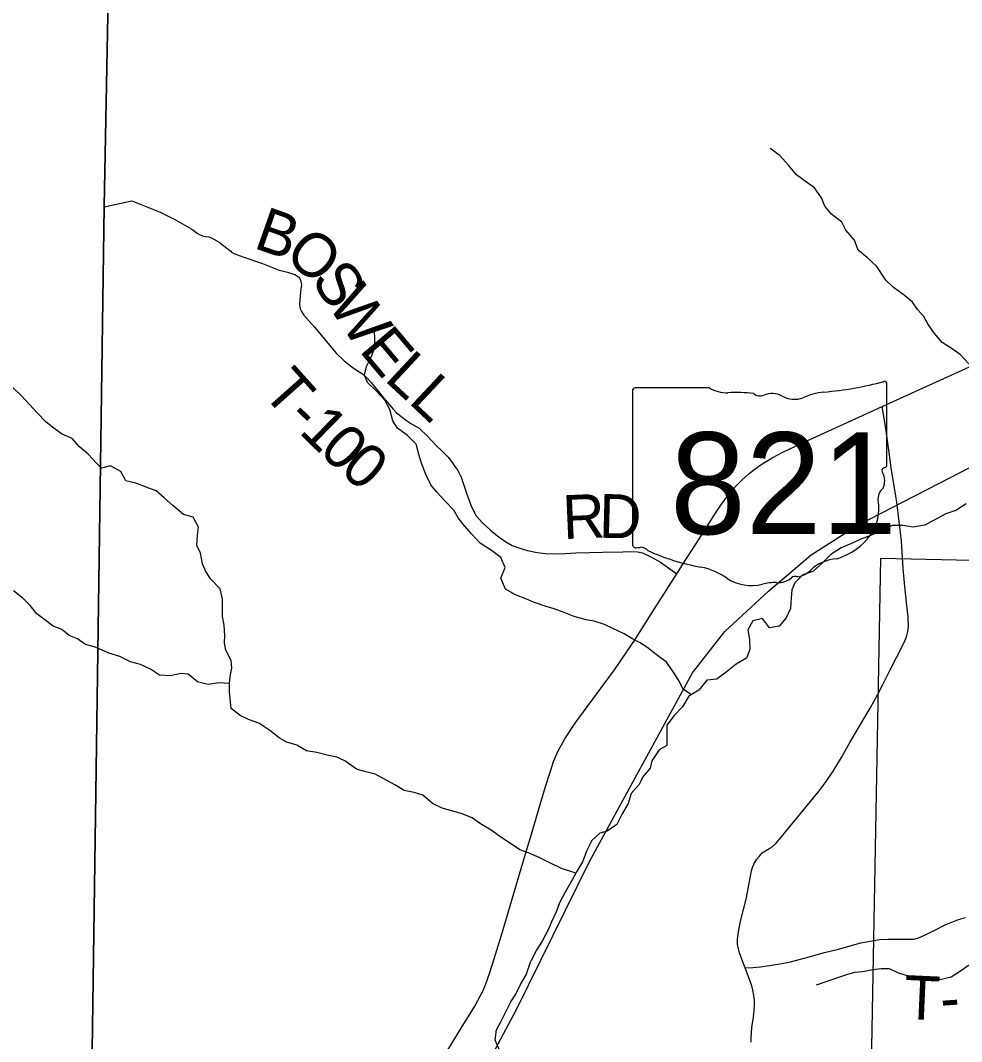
# Model space of a CAD drawing. Extents: x 0 to 34, y 0 to 22.
# Drawn here: x 5.288 to 6.508, y 17.948 to 19.271 of the extents above; entities that cross this region are included whole.
import ezdxf

# ---------------------------------------------------------------- set-up
doc = ezdxf.new("R2010")
doc.units = 0
for name, color, linetype in [('GM_X_Corporation', 7, 'Continuous'), ('GM_X_County_Road', 7, 'Continuous'), ('GM_X_Minor_River', 7, 'Continuous'), ('GM_X_Rail_Line', 7, 'Continuous'), ('GM_X_State_Location', 7, 'Continuous'), ('GM_X_State_Route', 7, 'Continuous'), ('GM_X_State_Shield', 7, 'Continuous'), ('GM_X_Township_Road', 7, 'Continuous'), ('GM_X_Township_Road_Text', 7, 'Continuous')]:
    doc.layers.add(name, color=color, linetype=linetype)

msp = doc.modelspace()

# ---------------------------------------------------------------- linework, layer by layer
at = {"layer": 'GM_X_Corporation'}
for points in [[(5.3543, 16.3597), (5.3699, 17.5116), (5.3717, 17.6123), (5.3798, 17.8448), (5.3967, 19.0299), (5.4062, 19.5263), (5.4087, 19.6104), (5.6993, 19.6004), (6.6444, 19.5688), (7.0794, 19.5596), (7.3097, 19.5503), (7.9584, 19.5358), (7.9795, 19.5354), (8.4033, 19.5268)], [(8.4033, 19.5268), (7.9795, 19.5354), (7.9584, 19.5358), (7.3097, 19.5503), (7.0794, 19.5596), (6.6444, 19.5688), (5.6993, 19.6004), (5.4087, 19.6104), (5.4062, 19.5263), (5.3967, 19.0299), (5.3798, 17.8448), (5.3717, 17.6123), (5.3699, 17.5116), (5.3543, 16.3597)], [(8.4033, 19.5268), (7.9795, 19.5354), (7.9584, 19.5358), (7.3097, 19.5503), (7.0794, 19.5596), (6.6444, 19.5688), (5.6993, 19.6004), (5.4087, 19.6104), (5.4062, 19.5263), (5.3967, 19.0299), (5.3798, 17.8448), (5.3717, 17.6123), (5.3699, 17.5116), (5.3543, 16.3597)], [(3.3691, 19.5041), (3.3642, 18.7005), (3.7035, 18.69), (4.377, 18.6713), (4.3782, 18.6502), (4.3768, 18.4091), (4.37, 17.9048), (4.3669, 17.8198), (4.3705, 17.6391), (4.6401, 17.6298), (5.3717, 17.6123), (5.3798, 17.8448), (5.3967, 19.0299), (5.4062, 19.5263)]]:
    msp.add_lwpolyline(points, dxfattribs=at)
msp.add_lwpolyline([(6.4033, 18.5738), (7.4054, 18.552), (7.375, 17.5696), (6.3854, 17.5878)], close=True, dxfattribs=at)
at = {"layer": 'GM_X_County_Road'}
msp.add_lwpolyline([(6.2353, 17.9468), (6.2351, 17.9523), (6.2363, 17.9656), (6.2385, 17.9792), (6.2393, 17.9881), (6.2396, 17.9961), (6.2395, 18.0013), (6.2387, 18.0071), (6.2375, 18.0142), (6.2361, 18.0199), (6.2276, 18.0429), (6.224, 18.0516), (6.2219, 18.0579), (6.2202, 18.0625), (6.2189, 18.0678), (6.2177, 18.0736), (6.2176, 18.0801), (6.2193, 18.0922), (6.222, 18.1053), (6.2288, 18.1322), (6.2359, 18.1687), (6.237, 18.1731), (6.2388, 18.1775), (6.2426, 18.1841), (6.246, 18.188), (6.2495, 18.192), (6.2593, 18.1981), (6.2625, 18.2), (6.2678, 18.2046), (6.2744, 18.2124), (6.322, 18.2709), (6.3327, 18.2846), (6.3418, 18.2978), (6.3523, 18.3158), (6.3634, 18.3351), (6.3897, 18.3797), (6.3991, 18.397), (6.4061, 18.4102), (6.4156, 18.4291), (6.4236, 18.4454), (6.4335, 18.4649), (6.4368, 18.4722), (6.4383, 18.4791), (6.4393, 18.4853), (6.4388, 18.4979), (6.4366, 18.5167), (6.4346, 18.5375), (6.4324, 18.5608), (6.43, 18.5965), (6.424, 18.6468), (6.4169, 18.6913), (6.4141, 18.711), (6.4093, 18.7451), (6.4052, 18.7704)], dxfattribs=at)
at = {"layer": 'GM_X_Minor_River'}
for points in [[(6.5174, 18.8259), (6.506, 18.838), (6.4958, 18.8452), (6.483, 18.8536), (6.4728, 18.8653), (6.4641, 18.8775), (6.4589, 18.887), (6.4509, 18.8964), (6.4442, 18.9059), (6.4336, 18.915), (6.4196, 18.9249), (6.4098, 18.9344), (6.3981, 18.9519), (6.386, 18.9632), (6.374, 18.9731), (6.3691, 18.986), (6.3581, 18.9989), (6.3528, 19.0095), (6.3396, 19.0198), (6.3306, 19.03), (6.3264, 19.041), (6.3174, 19.0539), (6.3072, 19.0611), (6.294, 19.071), (6.2838, 19.0835), (6.2725, 19.096), (6.26, 19.1048)], [(6.1578, 18.3969), (6.1471, 18.4044), (6.1407, 18.4166), (6.1339, 18.4276), (6.1256, 18.4393), (6.1124, 18.4492), (6.1003, 18.4587), (6.0905, 18.4648), (6.0807, 18.4701), (6.0709, 18.4758), (6.0561, 18.483), (6.0452, 18.488), (6.032, 18.4925), (6.0214, 18.494), (6.0059, 18.4986), (5.993, 18.5036), (5.9798, 18.5085), (5.9696, 18.5115), (5.9534, 18.5169), (5.9432, 18.5214), (5.9299, 18.5264), (5.9171, 18.534), (5.9107, 18.548), (5.9164, 18.562), (5.9107, 18.5749), (5.8987, 18.584), (5.8839, 18.5935), (5.873, 18.6057), (5.8639, 18.6159), (5.8556, 18.6262), (5.85, 18.6364), (5.8387, 18.6478), (5.8277, 18.6596), (5.8202, 18.669), (5.8141, 18.6816), (5.8085, 18.696), (5.8051, 18.707), (5.801, 18.7217), (5.7897, 18.7328), (5.7768, 18.7426), (5.7708, 18.7521), (5.767, 18.7665), (5.7603, 18.7787), (5.7497, 18.7904), (5.738, 18.8018), (5.7342, 18.8113), (5.7369, 18.8223), (5.7433, 18.8355), (5.7471, 18.8461), (5.7475, 18.8568), (5.7472, 18.87)], [(5.3873, 18.6967), (5.3761, 18.7087), (5.3647, 18.7184), (5.3551, 18.7293), (5.3415, 18.7352), (5.3316, 18.7423), (5.3217, 18.7501), (5.3095, 18.7629), (5.3003, 18.7726), (5.2893, 18.785), (5.2782, 18.7951)], [(6.0081, 18.1659), (5.9894, 18.1719), (5.9743, 18.1791), (5.9607, 18.186), (5.9474, 18.1917), (5.9354, 18.1962), (5.9233, 18.2042), (5.9123, 18.2114), (5.8983, 18.2213), (5.8847, 18.2296), (5.8738, 18.2376), (5.8594, 18.2433), (5.8485, 18.246), (5.8349, 18.2502), (5.8224, 18.2559), (5.8096, 18.2669), (5.7986, 18.2703), (5.7854, 18.273), (5.7733, 18.2802), (5.7601, 18.2878), (5.748, 18.2939), (5.734, 18.2977), (5.7238, 18.3007), (5.7087, 18.3114), (5.6985, 18.3163), (5.6856, 18.3186), (5.6724, 18.322), (5.6592, 18.3243), (5.6463, 18.3315), (5.6335, 18.3357), (5.6237, 18.341), (5.6116, 18.3505), (5.5972, 18.36), (5.5836, 18.365), (5.573, 18.3699), (5.5613, 18.3794), (5.5602, 18.3919), (5.5591, 18.4014), (5.5591, 18.4112), (5.5599, 18.4207), (5.5622, 18.4313), (5.5615, 18.4412), (5.5543, 18.4548), (5.5528, 18.4643), (5.5532, 18.4738), (5.5521, 18.4871), (5.5502, 18.4984), (5.5503, 18.5212), (5.5469, 18.5341), (5.5348, 18.5466), (5.5284, 18.5568), (5.5243, 18.5667), (5.5216, 18.5803), (5.5167, 18.5906), (5.5179, 18.6039), (5.5191, 18.6141), (5.5119, 18.627), (5.4994, 18.6308), (5.4858, 18.6422), (5.4745, 18.652), (5.4643, 18.6612), (5.4511, 18.6661), (5.4379, 18.6714), (5.425, 18.6741), (5.4182, 18.6862), (5.405, 18.6935), (5.3933, 18.6908), (5.3873, 18.6967)], [(6.514, 18.6443), (6.5007, 18.6356), (6.4875, 18.6315), (6.4727, 18.6231), (6.4599, 18.6167), (6.4451, 18.6141), (6.4319, 18.6164), (6.4179, 18.6164), (6.405, 18.6103), (6.3914, 18.6039), (6.3774, 18.5986), (6.3653, 18.5929), (6.352, 18.5873), (6.3384, 18.5789), (6.3274, 18.5676), (6.3153, 18.5566), (6.3021, 18.5525), (6.2918, 18.5422), (6.288, 18.5328), (6.2873, 18.5225), (6.2861, 18.5089), (6.2808, 18.4968), (6.2717, 18.4858), (6.2592, 18.4839), (6.2498, 18.4957), (6.2373, 18.4926), (6.2312, 18.4813), (6.2331, 18.4684), (6.2338, 18.4555), (6.2293, 18.4445), (6.216, 18.4366), (6.2028, 18.4264), (6.1906, 18.4173)], [(5.3837, 18.4593), (5.3726, 18.462), (5.3623, 18.4694), (5.3513, 18.4739), (5.3418, 18.4814), (5.3308, 18.4858), (5.3198, 18.494), (5.3095, 18.5019), (5.3007, 18.5127), (5.2912, 18.5221), (5.2794, 18.5315)], [(5.5592, 18.4117), (5.5455, 18.4124), (5.5315, 18.4101), (5.5175, 18.4136), (5.5058, 18.4238), (5.496, 18.4246), (5.4828, 18.4216), (5.4684, 18.4224), (5.4567, 18.4303), (5.4439, 18.4364), (5.431, 18.4395), (5.417, 18.4467), (5.4027, 18.4509), (5.3902, 18.4566), (5.3837, 18.4593)], [(6.1906, 18.4173), (6.1778, 18.4161), (6.1675, 18.4029), (6.1547, 18.395), (6.1463, 18.3813), (6.1357, 18.37), (6.1259, 18.3575), (6.1258, 18.3442), (6.1262, 18.3313), (6.116, 18.3256), (6.1065, 18.3112), (6.1046, 18.3018), (6.0951, 18.2908), (6.0902, 18.2806), (6.0799, 18.2692), (6.0761, 18.2559), (6.0682, 18.2427), (6.0613, 18.229), (6.0488, 18.22), (6.039, 18.2177), (6.0288, 18.2079), (6.0223, 18.195), (6.0166, 18.1806), (6.009, 18.1677), (6.0026, 18.1552), (5.9942, 18.1412), (5.9874, 18.1283), (5.9825, 18.1158), (5.9764, 18.1029), (5.9726, 18.0931), (5.965, 18.0787), (5.957, 18.0662), (5.9497, 18.0517)], [(5.9102, 17.9345), (5.9033, 17.9492), (5.9052, 17.9629), (5.9108, 17.9731), (5.9176, 17.9868), (5.924, 17.999), (5.9301, 18.0088), (5.9365, 18.0214), (5.9436, 18.0339), (5.9497, 18.0517)], [(6.5473, 18.058), (6.5308, 18.0512), (6.5172, 18.0462), (6.5066, 18.0386), (6.4945, 18.031), (6.4839, 18.0283), (6.4707, 18.0259), (6.4578, 18.0282), (6.446, 18.0308), (6.4351, 18.0334), (6.4256, 18.0368), (6.4146, 18.0417), (6.404, 18.0416), (6.393, 18.0404), (6.3801, 18.0381), (6.3692, 18.0369), (6.3589, 18.0339), (6.3332, 18.0254), (6.3196, 18.0208)]]:
    msp.add_lwpolyline(points, dxfattribs=at)
at = {"layer": 'GM_X_Rail_Line'}
msp.add_lwpolyline([(5.8084, 17.7591), (5.9312, 17.9893), (6.0258, 18.181), (6.1592, 18.4254), (6.2013, 18.4788), (6.2577, 18.5311), (6.3132, 18.5784), (6.3726, 18.6165), (6.493, 18.6782), (6.6221, 18.7453)], dxfattribs=at)
at = {"layer": 'GM_X_State_Route'}
for points in [[(5.9596, 18.2473), (5.9619, 18.2548), (5.9687, 18.2783), (5.9751, 18.2978), (5.9793, 18.3105), (5.985, 18.3242), (5.9938, 18.3398), (6.0074, 18.3601), (6.0228, 18.3815), (6.0582, 18.4292), (6.0843, 18.4671), (6.1063, 18.5024), (6.1389, 18.5535), (6.1506, 18.5721), (6.1644, 18.5935), (6.189, 18.6323), (6.1969, 18.644), (6.2006, 18.6492), (6.2047, 18.6546), (6.2111, 18.6624), (6.2172, 18.6692), (6.2231, 18.675), (6.2278, 18.6793), (6.2328, 18.6836), (6.2399, 18.6892), (6.2469, 18.6944), (6.2626, 18.7039), (6.2697, 18.7078), (6.2764, 18.7114), (6.3001, 18.7227), (6.4052, 18.7704), (6.5279, 18.8265)], [(5.9429, 18.191), (5.9491, 18.212), (5.9596, 18.2473)], [(5.7111, 17.6698), (5.7186, 17.7061), (5.7227, 17.7255), (5.7255, 17.7355), (5.7284, 17.7436), (5.7329, 17.7559), (5.7407, 17.7702), (5.7555, 17.7949), (5.7771, 17.83), (5.7923, 17.8552), (5.8322, 17.9203), (5.8596, 17.9649), (5.877, 17.9936), (5.8851, 18.0081), (5.888, 18.0139), (5.891, 18.0209), (5.8968, 18.0369), (5.9024, 18.0548), (5.913, 18.0899), (5.9252, 18.1309), (5.9429, 18.191)]]:
    msp.add_lwpolyline(points, dxfattribs=at)
at = {"layer": 'GM_X_State_Shield'}
for p, q in [((6.1814, 18.7947), (6.0849, 18.7947)), ((6.4113, 18.6949), (6.4113, 18.7996)), ((6.0817, 18.7912), (6.0817, 18.5911)), ((6.4112, 18.695), (6.4113, 18.6949))]:
    msp.add_line(p, q, dxfattribs=at)
for centre, major_axis, start_param, end_param in [((6.0854, 18.7916), (0.00382, 0), 1.712693, 3.28349), ((6.2044, 18.8179), (0.037, 0), 4.042523, 4.731795), ((6.2939, 19.0675), (0.3495, 0), 4.814394, 5.042369), ((6.4076, 18.8001), (0.00367, 0), 6.141152, 7.989035), ((6.2167, 18.6823), (0.133, 0), 1.404758, 1.657858), ((6.2469, 18.7927), (0.0107, 0), 3.836095, 5.185415), ((6.2626, 18.7696), (0.0222, 0), 0.950623, 2.079405), ((6.2912, 18.8013), (0.0267, 0), 4.081561, 5.145723), ((6.3384, 18.7335), (0.0703, 0), 1.699011, 2.107814), ((6.4104, 18.6872), (0.00568, 0), 1.883978, 3.671073), ((6.4073, 18.6945), (0.00393, 0), 5.05454, 6.418171), ((6.3743, 18.674), (0.0341, 0), 5.934695, 6.695948), ((6.4244, 18.6511), (0.0248, 0), 2.387724, 3.262537), ((6.3134, 18.6378), (0.0874, 0), 5.101752, 6.440018), ((6.0855, 18.5907), (0.00385, 0), 3.00124, 4.508301), ((6.0861, 18.6111), (0.0294, 0), 4.665946, 4.897461), ((6.0921, 18.5796), (0.0106, 0), 0.519207, 1.627899), ((6.2259, 18.7594), (0.2524, 0), 4.195997, 4.488961), ((6.3503, 18.5349), (0.0479, 0), 1.647645, 2.488434), ((6.1507, 18.5012), (0.079, 0), 0.823519, 1.323587), ((6.2896, 18.5717), (0.0282, 0), 4.937069, 5.64225), ((6.2361, 18.5786), (0.0501, 0), 4.026481, 4.996735), ((6.265, 18.5094), (0.0412, 0), 1.495662, 1.94098), ((6.2687, 18.5636), (0.0267, 0), 4.691044, 5.507374), ((6.2928, 18.5442), (0.00752, 0), 1.147584, 2.315152)]:
    msp.add_ellipse(centre, major_axis=major_axis, ratio=0.8, start_param=start_param, end_param=end_param, dxfattribs=at)
at = {"layer": 'GM_X_Township_Road'}
for points in [[(5.3969, 19.0293), (5.4326, 19.037), (5.4694, 19.0223), (5.4893, 19.0125), (5.5104, 19.0003), (5.514, 18.9977), (5.5171, 18.9951), (5.5203, 18.9933), (5.5242, 18.9919), (5.5281, 18.9909), (5.5322, 18.9903), (5.5357, 18.9893), (5.5459, 18.9834), (5.552, 18.979), (5.5575, 18.9744), (5.5608, 18.9717)], [(5.5608, 18.9717), (5.5624, 18.9703), (5.5684, 18.9674), (5.5778, 18.9641), (5.602, 18.9558), (5.6236, 18.9472), (5.629, 18.9458), (5.6342, 18.9445), (5.6412, 18.9426), (5.6438, 18.9418), (5.6461, 18.9405), (5.6487, 18.9387), (5.6504, 18.9364), (5.6516, 18.9331), (5.6524, 18.9279), (5.6517, 18.923), (5.6507, 18.9142), (5.65, 18.9032), (5.6509, 18.8972), (5.6526, 18.8938), (5.6555, 18.8889), (5.6695, 18.8732), (5.698, 18.8394), (5.708, 18.8297), (5.7178, 18.8221), (5.7248, 18.8174), (5.7315, 18.8131), (5.7371, 18.8079), (5.7426, 18.8016), (5.7588, 18.7816), (5.7715, 18.767), (5.7758, 18.7622), (5.7829, 18.7566), (5.7887, 18.7525), (5.7952, 18.7483), (5.8051, 18.7423), (5.8162, 18.7319), (5.8215, 18.7261), (5.8269, 18.7199), (5.8348, 18.7126), (5.8424, 18.7048), (5.847, 18.6994), (5.8505, 18.6943), (5.8551, 18.6876), (5.8595, 18.6792), (5.8663, 18.6583), (5.873, 18.6406), (5.8791, 18.6288), (5.8871, 18.6198), (5.8971, 18.6108), (5.9068, 18.6027), (5.9173, 18.5952), (5.9254, 18.5903), (5.9343, 18.5872), (5.9453, 18.5841), (5.958, 18.5812), (5.9691, 18.58), (5.9834, 18.5796), (5.9944, 18.5802), (6.0081, 18.5809), (6.0428, 18.5818), (6.069, 18.5824), (6.0782, 18.5826), (6.0881, 18.5821), (6.0944, 18.5808), (6.1063, 18.5755), (6.1176, 18.5687), (6.1389, 18.5535)], [(6.2276, 18.0429), (6.2373, 18.0437), (6.2472, 18.0445), (6.2592, 18.0461), (6.2749, 18.0487), (6.2862, 18.051), (6.2976, 18.0539), (6.3103, 18.0574), (6.3304, 18.0629), (6.3486, 18.0672), (6.3775, 18.0753), (6.3895, 18.0778), (6.4015, 18.0796), (6.4126, 18.0803), (6.4301, 18.0803), (6.4378, 18.0801), (6.4462, 18.0804), (6.451, 18.0815), (6.4567, 18.0837), (6.4725, 18.0916), (6.4878, 18.0993), (6.4953, 18.1024), (6.5042, 18.1058), (6.5133, 18.1085)]]:
    msp.add_lwpolyline(points, dxfattribs=at)

# ---------------------------------------------------------------- texts
at = {"layer": 'GM_X_State_Location'}
for s in ['s', 'r']:
    msp.add_text(s, height=0.000189, dxfattribs=at).set_placement((6.2428, 18.6779))
msp.add_text('821', height=0.000189, rotation=0, dxfattribs=at).set_placement((6.1759, 18.6641))
at = {"layer": 'GM_X_State_Shield'}
msp.add_text('821', height=0.13184, dxfattribs=at).set_placement((6.1302, 18.6052))
at = {"layer": 'GM_X_Township_Road_Text'}
for s, rotation, p in [('B', 340.6591, (5.5889, 18.9766)), ('O', 320.2103, (5.6283, 18.9638)), ('S', 303.839, (5.6639, 18.935)), ('W', 303.9521, (5.6853, 18.903)), ('E', 310.1964, (5.7261, 18.843)), ('L', 317.127, (5.7587, 18.8052)), ('T', 311.7435, (5.6, 18.7884)), ('L', 316.7397, (5.7898, 18.7763)), ('-', 315.4195, (5.631, 18.7538)), ('1', 315.6517, (5.6478, 18.7372)), ('0', 316.6176, (5.6736, 18.712)), ('0', 318.6466, (5.7007, 18.6865)), ('R', 2.4792, (5.992, 18.5986)), ('D', 358.5464, (6.0376, 18.6006)), ('T', 357.4192, (6.4324, 17.977)), ('-', 4.0323, (6.482, 17.9752))]:
    msp.add_text(s, height=0.0568, rotation=rotation, dxfattribs=at).set_placement(p)

doc.saveas('drawing.dxf')
